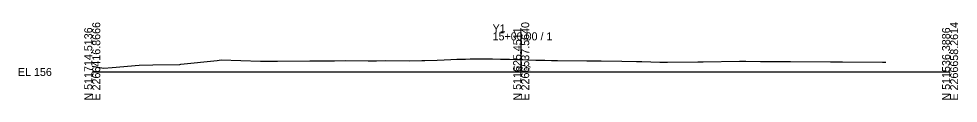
# Model space of a CAD drawing. Extents: x -516 to 303, y -10 to 5017.
# Drawn here: x -25.7 to 302.8, y 4990.3 to 5017.4 of the extents above; entities that cross this region are included whole.
import ezdxf

# ---------------------------------------------------------------- set-up
doc = ezdxf.new("R2010")
doc.units = 0
for name, color, linetype in [('Default', 7, 'Continuous'), ('Exist Cross Section Cell', 7, 'Continuous'), ('Exist XS Center Line Elevation Label', 7, 'Continuous'), ('Exist XS Ground Line', 7, 'Continuous')]:
    doc.layers.add(name, color=color, linetype=linetype)

msp = doc.modelspace()

# ---------------------------------------------------------------- linework, layer by layer
at = {"layer": 'Exist Cross Section Cell'}
for p, q in [((150, 5000), (150, 5013.87)), ((0, 5000), (150, 5000)), ((150, 5000), (300, 5000))]:
    msp.add_line(p, q, dxfattribs=at)
at = {"layer": 'Exist XS Ground Line'}
msp.add_lwpolyline([(0, 5002.08), (4.02, 5001.39), (6.91, 5001.56), (16.45, 5002.35), (21.18, 5002.55), (30.6, 5002.67), (31.01, 5002.7), (43.69, 5004.05), (45.1, 5004.2), (58.83, 5003.83), (62.83, 5003.76), (64.81, 5003.76), (76.08, 5003.91), (76.9, 5003.89), (78.23, 5003.9), (84.74, 5003.95), (88.71, 5003.97), (96.54, 5003.93), (99.4, 5003.95), (102.54, 5003.97), (111.04, 5003.92), (115.23, 5004.02), (116.27, 5004), (120.6, 5004.14), (123.08, 5004.29), (125.39, 5004.39), (127.54, 5004.44), (130.51, 5004.5), (132.17, 5004.57), (132.84, 5004.59), (133.96, 5004.6), (135.45, 5004.62), (136.55, 5004.62), (137.85, 5004.61), (139.96, 5004.58), (142.76, 5004.53), (143.2, 5004.52), (143.79, 5004.5), (145, 5004.47), (145.89, 5004.45), (147.99, 5004.39), (148.96, 5004.35), (150, 5004.32), (150.32, 5004.31), (152.18, 5004.27), (155.14, 5004.19), (156.4, 5004.16), (157.48, 5004.13), (158.29, 5004.1), (160.61, 5004.03), (161.56, 5003.98), (162.29, 5003.97), (162.74, 5003.97), (172.98, 5003.92), (174.88, 5003.9), (175.56, 5003.9), (176.09, 5003.9), (177.13, 5003.88), (177.99, 5003.88), (185.26, 5003.82), (190.37, 5003.72), (192.19, 5003.72), (198.49, 5003.47), (201.18, 5003.47), (211.82, 5003.54), (213.59, 5003.53), (226.35, 5003.76), (226.83, 5003.76), (227.29, 5003.76), (228.54, 5003.75), (233.74, 5003.72), (244.16, 5003.65), (258.12, 5003.59), (262.08, 5003.57), (262.38, 5003.58), (276.41, 5003.47), (277.47, 5003.46)], dxfattribs=at)

# ---------------------------------------------------------------- texts
at = {"layer": 'Default'}
msp.add_text('-', height=0.0001, dxfattribs=at).set_placement((0, 5000))
at = {"layer": 'Exist Cross Section Cell'}
for s, p in [('E 2266416.8666', (2.8, 4990)), ('E 2266537.5640', (152.8, 4990)), ('E 2266658.2614', (302.8, 4990)), ('N 511714.5136', (0, 4990)), ('N 511625.4511', (150, 4990)), ('N 511536.3886', (300, 4990))]:
    msp.add_text(s, height=2.8, rotation=90, dxfattribs=at).set_placement(p)
for s, p in [('Y1', (140, 5013.87)), ('15+00.00 / 1', (140, 5011.07)), ('EL 156', (-26, 4998.6))]:
    msp.add_text(s, height=2.8, dxfattribs=at).set_placement(p)
at = {"layer": 'Exist XS Center Line Elevation Label'}
msp.add_text('160.32', height=1.5, dxfattribs=at).set_placement((147.02, 5000.57))

doc.saveas('drawing.dxf')
